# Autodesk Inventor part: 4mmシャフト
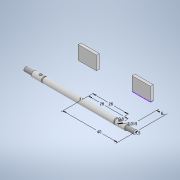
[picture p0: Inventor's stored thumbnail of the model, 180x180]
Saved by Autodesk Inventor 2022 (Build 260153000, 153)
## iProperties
Created: 2024-10
Part Number: 4mmシャフト
Material: 一般
Document SubType Name: Modeling
Designer: jsat7
Density: 1 g/cm^3
Appearance: 既定
Author: jsat7
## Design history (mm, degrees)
sketch "スケッチ1"
  geometry: L1 (0, 0)-(-40, 0); L2 (-40, 0)-(-40, -1.5); L3 (-40, -1.5)-(-34, -1.5); L4 (-34, -1.5)-(-34, -2); L5 (-34, -2)-(-26.8, -2); L6 (-26.8, -2)-(-26.8, -1.5); L7 (-26.8, -1.5)-(-26, -1.5); L8 (-26, -1.5)-(-26, -2); L9 (-26, -2)-(0, -2); L10 (0, -2)-(0, 0); L11 (-13, -26.74)-(-26.4, -26.74); L12 (-26.4, -26.74)-(-26.4, -24.724); L13 (-26.4, -24.724)-(-13, -24.724); L14 (-13, -24.724)-(-13, -26.74); C1 r 1.009 at (-29, 0)
  constraints: 28 end point, 8 perpendicular, 5 point on line, 2 horizontal, 2 parallel, 1 centre point
  dimensions: "d0" = 40 distance of L1.end L1.start; "d1" = 6 distance of L2.end L3.end; "d2" = 0.8 distance between parallel lines of L6 L8; "d3" = 2 distance between parallel lines of L1 L9; "d4" = 1.5 distance between parallel lines of L1 L3; "d5" = 26 distance between parallel lines of L10 L8; "d6" = 29 distance of L1.start C1.centre; "d7" = 2.01871 diameter of C1
revolve "回転1" stored, may be unused: angle "d8" = 90 deg
extrude "押し出し1" join sketch "スケッチ1" distance "d9" = 10; taper "d10" = 0 deg
sketch "スケッチ2"
  geometry: C1 r 1 at (29, 0); 1 further point
  constraints: 1 centre point
  dimensions: "d11" = 29 distance of point (0, 0) C1.centre; "d12" = 2 diameter of C1
extrude "押し出し2" cut sketch "スケッチ2" distance "d13" = 20; taper "d14" = 0 deg
mirror "ミラー1"
feature "ねじ1" dims "d15" = 6, "d16" = 0
feature "ねじ2" dims "d17" = 6, "d18" = 0
node "ソリッド1"
